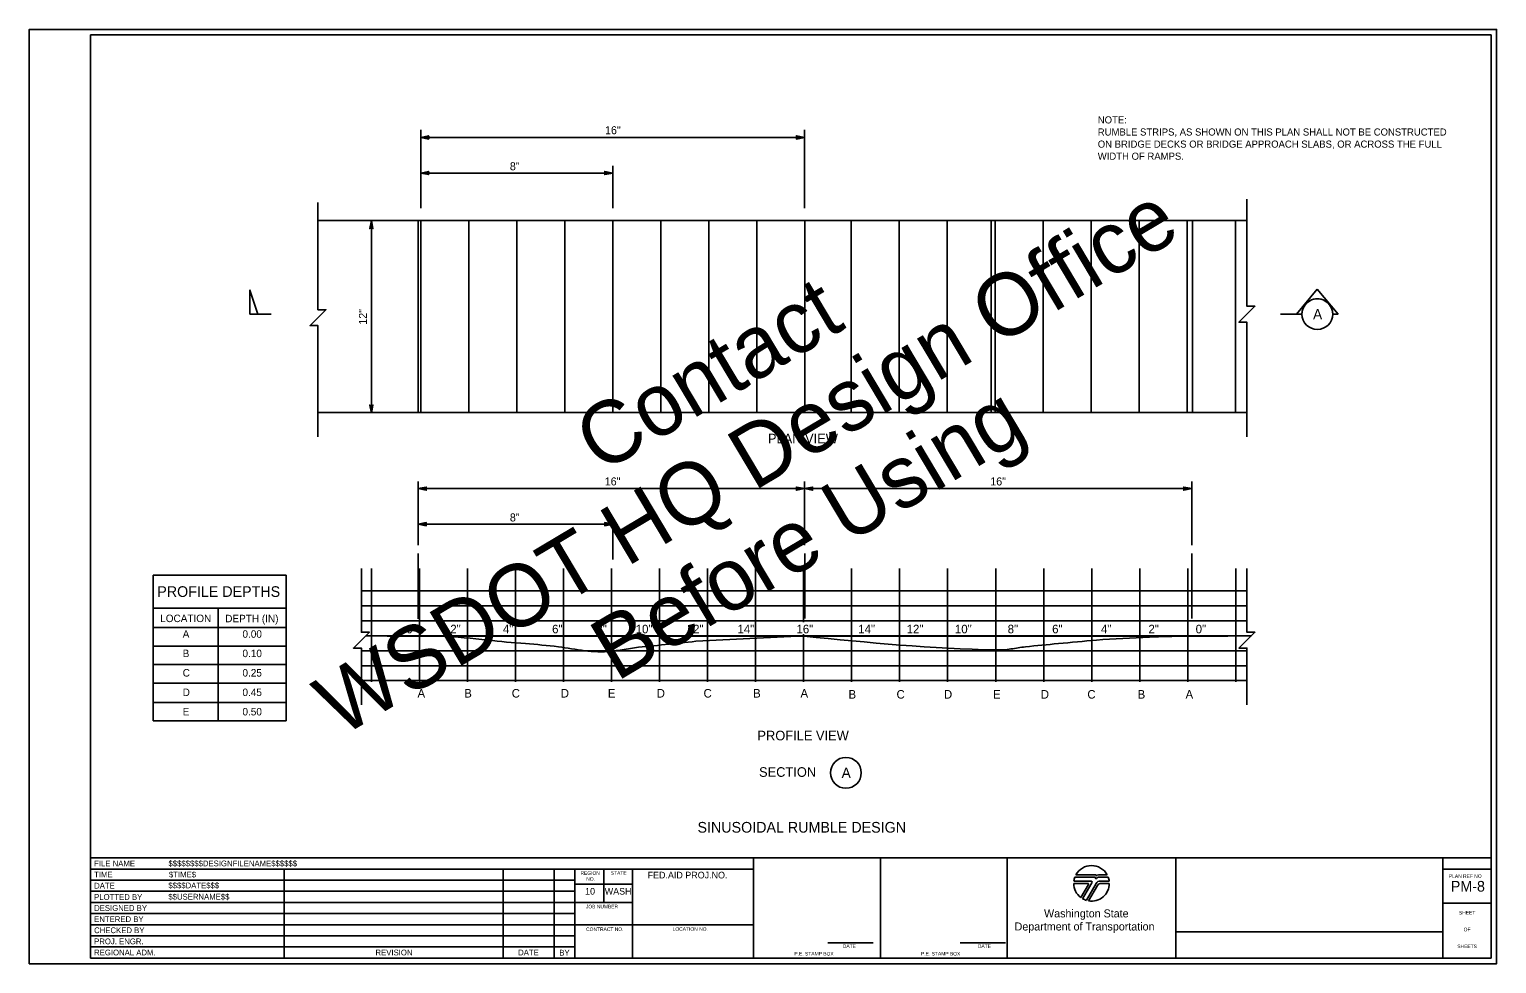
# Model space of a CAD drawing. Extents: x 100019.3 to 100035.8, y 99999.9 to 100024.4.
# Drawn here: x 100019.31 to 100035.81, y 99999.94 to 100010.44 of the extents above; entities that cross this region are included whole.
import ezdxf

# ---------------------------------------------------------------- set-up
doc = ezdxf.new("R2010")
doc.units = 0
for name, color, linetype in [('Level 10', 7, 'Continuous'), ('Level 15', 7, 'Continuous'), ('Level 16', 7, 'Continuous'), ('Level 20', 7, 'Continuous'), ('Level 22', 7, 'Continuous'), ('Level 25', 7, 'Continuous'), ('SH_GI_PlotLimits', 7, 'Continuous'), ('SH_GI_SheetBorder', 7, 'Continuous'), ('SH_GI_SheetTextInCells', 7, 'Continuous'), ('SH_GI_TitleBlockText', 7, 'Continuous'), ('SH_GI_WSDOTLogo', 7, 'Continuous')]:
    doc.layers.add(name, color=color, linetype=linetype)

msp = doc.modelspace()

# ---------------------------------------------------------------- linework, layer by layer
at = {"layer": 'Level 10'}
for p, q in [((100023.685, 100008.29), (100023.685, 100006.13)), ((100025.874, 100008.29), (100025.874, 100006.13)), ((100028.034, 100008.29), (100028.034, 100006.13)), ((100030.174, 100008.29), (100030.174, 100006.13)), ((100032.391, 100008.29), (100032.391, 100006.13)), ((100023.685, 100004.547), (100023.685, 100003.811)), ((100028.034, 100004.547), (100028.034, 100003.815)), ((100032.385, 100004.547), (100032.385, 100003.815))]:
    msp.add_line(p, q, dxfattribs=at)
at = {"layer": 'Level 15'}
for p, q in [((100023.713, 100008.427), (100023.713, 100009.308)), ((100028.029, 100008.427), (100028.029, 100009.308)), ((100028.029, 100009.223), (100023.713, 100009.223)), ((100025.874, 100008.823), (100023.713, 100008.823)), ((100025.874, 100008.427), (100025.874, 100008.903)), ((100023.159, 100008.29), (100023.159, 100006.124)), ((100025.874, 100008.29), (100025.874, 100006.13)), ((100023.685, 100004.641), (100023.685, 100005.355)), ((100028.029, 100004.641), (100028.029, 100005.355)), ((100032.385, 100005.355), (100032.385, 100004.64)), ((100028.029, 100005.276), (100023.685, 100005.276)), ((100032.385, 100005.276), (100028.029, 100005.276)), ((100025.874, 100004.876), (100023.685, 100004.876)), ((100025.874, 100004.48), (100025.874, 100004.956))]:
    msp.add_line(p, q, dxfattribs=at)
for points in [[(100023.713, 100009.223), (100023.803, 100009.205), (100023.799, 100009.223), (100023.803, 100009.241)], [(100028.029, 100009.223), (100027.938, 100009.241), (100027.943, 100009.223), (100027.938, 100009.205)], [(100023.713, 100008.823), (100023.803, 100008.805), (100023.799, 100008.823), (100023.803, 100008.841)], [(100025.874, 100008.823), (100025.783, 100008.841), (100025.787, 100008.823), (100025.783, 100008.805)], [(100023.159, 100008.29), (100023.176, 100008.199), (100023.159, 100008.203), (100023.141, 100008.199)], [(100023.159, 100006.124), (100023.176, 100006.215), (100023.159, 100006.21), (100023.141, 100006.215)], [(100023.685, 100005.276), (100023.776, 100005.258), (100023.771, 100005.276), (100023.776, 100005.294)], [(100028.029, 100005.276), (100027.938, 100005.294), (100027.943, 100005.276), (100027.938, 100005.258)], [(100028.029, 100005.276), (100028.12, 100005.258), (100028.115, 100005.276), (100028.12, 100005.294)], [(100032.385, 100005.276), (100032.294, 100005.294), (100032.299, 100005.276), (100032.294, 100005.258)], [(100023.685, 100004.876), (100023.776, 100004.858), (100023.771, 100004.876), (100023.776, 100004.894)], [(100025.874, 100004.876), (100025.783, 100004.894), (100025.787, 100004.876), (100025.783, 100004.858)]]:
    msp.add_lwpolyline(points, close=True, dxfattribs=at)
for points in [[(100022.558, 100008.491), (100022.558, 100007.286), (100022.647, 100007.286), (100022.469, 100007.108), (100022.558, 100007.108), (100022.558, 100005.857)], [(100033.004, 100008.529), (100033.004, 100007.325), (100033.094, 100007.325), (100032.915, 100007.146), (100033.004, 100007.146), (100033.004, 100005.857)], [(100023.047, 100004.378), (100023.047, 100003.662), (100023.136, 100003.662), (100022.957, 100003.483), (100023.047, 100003.483), (100023.047, 100002.847)], [(100033.004, 100004.378), (100033.004, 100003.662), (100033.094, 100003.662), (100032.915, 100003.483), (100033.004, 100003.483), (100033.004, 100002.847)]]:
    msp.add_lwpolyline(points, dxfattribs=at)
at = {"layer": 'Level 20'}
for p, q in [((100033.796, 100007.516), (100033.562, 100007.237)), ((100034.029, 100007.237), (100033.796, 100007.516)), ((100022.033, 100007.237), (100021.793, 100007.237)), ((100033.623, 100007.237), (100033.383, 100007.237)), ((100033.562, 100007.237), (100033.623, 100007.237)), ((100033.968, 100007.237), (100034.029, 100007.237)), ((100021.435, 100003.931), (100021.435, 100002.668))]:
    msp.add_line(p, q, dxfattribs=at)
msp.add_lwpolyline([(100021.883, 100007.237), (100021.793, 100007.507), (100021.793, 100007.237)], close=True, dxfattribs=at)
for centre in [(100033.796, 100007.237), (100028.495, 100002.082)]:
    msp.add_circle(centre, 0.173, dxfattribs=at)
msp.add_arc((100033.796, 100007.237), 0.173, 359.9978, 180.0022, dxfattribs=at)
at = {"layer": 'Level 22'}
for p, q in [((100023.401, 100003.618), (100028.019, 100003.618)), ((100032.128, 100003.618), (100027.217, 100003.618))]:
    msp.add_line(p, q, dxfattribs=at)
for points in [[(100023.096, 100003.622), (100023.735, 100003.618), (100023.938, 100003.618), (100024.466, 100003.573), (100024.892, 100003.534), (100025.262, 100003.498), (100025.852, 100003.447), (100025.931, 100003.458), (100026.119, 100003.487), (100026.464, 100003.523), (100026.809, 100003.56), (100027.416, 100003.59), (100028.027, 100003.618), (100028.041, 100003.618)], [(100032.791, 100003.618), (100032.312, 100003.618), (100031.908, 100003.607), (100031.311, 100003.573), (100030.884, 100003.534), (100030.514, 100003.498), (100030.432, 100003.487), (100030.35, 100003.474), (100030.268, 100003.464), (100030.186, 100003.463), (100028.027, 100003.618)]]:
    msp.add_spline(points, degree=3, dxfattribs=at)
at = {"layer": 'Level 25'}
for p, q in [((100022.558, 100008.29), (100033.004, 100008.29)), ((100023.713, 100008.29), (100023.713, 100006.13)), ((100024.253, 100008.29), (100024.253, 100006.13)), ((100024.794, 100008.29), (100024.794, 100006.13)), ((100025.334, 100008.29), (100025.334, 100006.13)), ((100026.414, 100008.29), (100026.414, 100006.13)), ((100026.954, 100008.29), (100026.954, 100006.13)), ((100027.494, 100008.29), (100027.494, 100006.13)), ((100028.554, 100008.29), (100028.554, 100006.13)), ((100029.094, 100008.29), (100029.094, 100006.13)), ((100029.634, 100008.29), (100029.634, 100006.13)), ((100030.13, 100008.29), (100030.13, 100006.13)), ((100030.714, 100008.29), (100030.714, 100006.13)), ((100031.254, 100008.29), (100031.254, 100006.13)), ((100031.794, 100008.29), (100031.794, 100006.13)), ((100032.334, 100008.29), (100032.334, 100006.13)), ((100032.874, 100008.29), (100032.874, 100006.13)), ((100022.558, 100006.13), (100033.004, 100006.13)), ((100023.159, 100003.106), (100023.159, 100004.378)), ((100023.699, 100003.106), (100023.699, 100004.378)), ((100024.239, 100003.106), (100024.239, 100004.378)), ((100024.779, 100003.106), (100024.779, 100004.378)), ((100025.319, 100003.106), (100025.319, 100004.378)), ((100025.859, 100003.106), (100025.859, 100004.378)), ((100026.399, 100003.106), (100026.399, 100004.378)), ((100026.939, 100003.106), (100026.939, 100004.378)), ((100027.479, 100003.106), (100027.479, 100004.378)), ((100028.019, 100003.774), (100028.019, 100004.378)), ((100028.559, 100003.106), (100028.559, 100004.378)), ((100029.099, 100003.106), (100029.099, 100004.378)), ((100029.639, 100003.106), (100029.639, 100004.378)), ((100030.179, 100003.106), (100030.179, 100004.378)), ((100030.719, 100003.106), (100030.719, 100004.378)), ((100031.259, 100003.106), (100031.259, 100004.378)), ((100031.799, 100003.106), (100031.799, 100004.378)), ((100032.339, 100003.106), (100032.339, 100004.378)), ((100032.879, 100003.106), (100032.879, 100004.378)), ((100023.047, 100004.126), (100029.099, 100004.126)), ((100029.099, 100004.126), (100033.004, 100004.126)), ((100020.706, 100003.931), (100022.199, 100003.931)), ((100023.047, 100003.958), (100029.099, 100003.958)), ((100029.099, 100003.958), (100033.004, 100003.958)), ((100020.706, 100003.715), (100022.199, 100003.715)), ((100023.047, 100003.79), (100029.099, 100003.79)), ((100029.099, 100003.79), (100033.004, 100003.79)), ((100023.096, 100003.622), (100029.099, 100003.622)), ((100028.019, 100003.106), (100028.019, 100003.639)), ((100029.099, 100003.622), (100033.054, 100003.622)), ((100020.706, 100003.507), (100022.199, 100003.507)), ((100023.047, 100003.454), (100029.099, 100003.454)), ((100029.099, 100003.454), (100033.004, 100003.454)), ((100020.706, 100003.299), (100022.199, 100003.299)), ((100023.047, 100003.286), (100029.099, 100003.286)), ((100029.099, 100003.286), (100033.004, 100003.286)), ((100020.706, 100003.09), (100022.199, 100003.09)), ((100023.047, 100003.118), (100029.099, 100003.118)), ((100029.099, 100003.118), (100033.004, 100003.118)), ((100020.706, 100002.874), (100022.199, 100002.874))]:
    msp.add_line(p, q, dxfattribs=at)
msp.add_lwpolyline([(100020.706, 100004.303), (100022.199, 100004.303), (100022.199, 100002.668), (100020.706, 100002.668)], close=True, dxfattribs=at)
at = {"layer": 'SH_GI_PlotLimits'}
msp.add_lwpolyline([(100019.312, 99999.937), (100035.812, 99999.937), (100035.812, 100010.437), (100019.312, 100010.437)], close=True, dxfattribs=at)
at = {"layer": 'SH_GI_SheetBorder'}
for p, q in [((100020, 100010.375), (100020, 100000)), ((100020, 100010.375), (100035.75, 100010.375)), ((100035.75, 100010.375), (100035.75, 100000)), ((100020, 100001.126), (100035.75, 100001.126)), ((100027.457, 100000), (100027.457, 100001.126)), ((100028.883, 100000), (100028.883, 100001.126)), ((100030.309, 100001.126), (100030.309, 100000)), ((100032.205, 100001.126), (100032.205, 100000)), ((100035.208, 100001.126), (100035.208, 100000)), ((100020, 100001.001), (100027.457, 100001.001)), ((100022.179, 100001.001), (100022.179, 100000)), ((100024.641, 100001.001), (100024.641, 100000)), ((100025.216, 100001.001), (100025.216, 100000)), ((100025.445, 100001.001), (100025.445, 100000)), ((100025.772, 100000.625), (100025.772, 100001.001)), ((100026.096, 100000), (100026.096, 100001.001)), ((100035.208, 100001.001), (100035.75, 100001.001)), ((100020, 100000.876), (100022.182, 100000.876)), ((100020, 100000.751), (100022.182, 100000.751)), ((100022.182, 100000.876), (100025.447, 100000.876)), ((100022.182, 100000.751), (100025.447, 100000.751)), ((100026.096, 100000.831), (100025.447, 100000.831)), ((100020, 100000.625), (100025.447, 100000.625)), ((100026.096, 100000.625), (100025.447, 100000.625)), ((100035.208, 100000.618), (100035.75, 100000.618)), ((100020, 100000.5), (100025.447, 100000.5)), ((100020, 100000.375), (100025.447, 100000.375)), ((100020, 100000.25), (100025.447, 100000.25)), ((100027.457, 100000.375), (100025.447, 100000.375)), ((100032.205, 100000.295), (100035.208, 100000.295)), ((100020, 100000.125), (100025.447, 100000.125)), ((100028.29, 100000.173), (100028.802, 100000.173)), ((100029.78, 100000.173), (100030.291, 100000.173)), ((100020, 100000), (100035.75, 100000))]:
    msp.add_line(p, q, dxfattribs=at)
at = {"layer": 'SH_GI_WSDOTLogo'}
for p, q in [((100031.289, 100000.909), (100031.07, 100000.909)), ((100031.303, 100000.935), (100031.081, 100000.935)), ((100031.433, 100000.935), (100031.335, 100000.935)), ((100031.445, 100000.909), (100031.343, 100000.909)), ((100031.343, 100000.909), (100031.343, 100000.909)), ((100031.057, 100000.84), (100031.215, 100000.84)), ((100031.059, 100000.866), (100031.25, 100000.866)), ((100031.222, 100000.828), (100031.136, 100000.681)), ((100031.261, 100000.846), (100031.157, 100000.667)), ((100031.199, 100000.649), (100031.309, 100000.839)), ((100031.224, 100000.643), (100031.324, 100000.816)), ((100031.356, 100000.866), (100031.456, 100000.866)), ((100031.365, 100000.839), (100031.457, 100000.839))]:
    msp.add_line(p, q, dxfattribs=at)
for centre, radius, start, end in [((100031.257, 100000.84), 0.2, 159.696, 172.5057), ((100031.257, 100000.84), 0.2, 28.4787, 151.532), ((100031.289, 100000.895), 0.0148, 327.8418, 89.9985), ((100031.343, 100000.861), 0.0484, 89.9953, 147.8238), ((100031.303, 100000.926), 0.00903, 329.8742, 90.0033), ((100031.335, 100000.907), 0.0287, 90.0072, 148.1676), ((100031.257, 100000.84), 0.2, 7.4943, 20.2941), ((100031.257, 100000.84), 0.2, 179.9986, 232.8433), ((100031.215, 100000.832), 0.0082, 329.7436, 90), ((100031.257, 100000.84), 0.2, 260.5455, 359.8086), ((100031.25, 100000.853), 0.0131, 329.7683, 90), ((100031.356, 100000.812), 0.0542, 90, 149.9974), ((100031.365, 100000.792), 0.0476, 90, 150.0543), ((100031.257, 100000.84), 0.2, 239.7929, 253.0448)]:
    msp.add_arc(centre, radius, start, end, dxfattribs=at)

# ---------------------------------------------------------------- texts
at = {"layer": 'Level 15'}
msp.add_text('SECTION ', height=0.108, dxfattribs=at).set_placement((100027.518, 100002.037))
at = {"layer": 'Level 16'}
for s, p in [('WSDOT HQ Design Office', (100022.812, 100002.475)), ('Contact ', (100025.736, 100005.438)), (' Before Using', (100025.692, 100002.968))]:
    msp.add_text(s, height=0.7, rotation=30.7778, dxfattribs=at).set_placement(p)
at = {"layer": 'Level 20'}
for s, height, p in [('16"', 0.09, (100025.786, 100009.259)), ('NOTE:', 0.08, (100031.327, 100009.38)), ('RUMBLE STRIPS, AS SHOWN ON THIS PLAN SHALL NOT BE CONSTRUCTED', 0.08, (100031.327, 100009.244)), ('ON BRIDGE DECKS OR BRIDGE APPROACH SLABS, OR ACROSS THE FULL', 0.08, (100031.327, 100009.108)), ('WIDTH OF RAMPS.', 0.08, (100031.327, 100008.972)), ('8"', 0.09, (100024.716, 100008.854)), ('A', 0.115, (100033.748, 100007.179)), ('PLAN VIEW', 0.108, (100027.618, 100005.785)), ('16"', 0.09, (100025.783, 100005.312)), ('16"', 0.09, (100030.118, 100005.312)), ('8"', 0.09, (100024.716, 100004.907)), ('PROFILE DEPTHS', 0.12, (100020.751, 100004.059)), ('LOCATION', 0.084, (100020.784, 100003.776)), ('DEPTH (IN)', 0.084, (100021.515, 100003.774)), ('0"', 0.096, (100023.552, 100003.65)), ('2"', 0.096, (100024.046, 100003.65)), ('4"', 0.096, (100024.638, 100003.65)), ('6"', 0.096, (100025.191, 100003.65)), ('8"', 0.096, (100025.689, 100003.65)), ('10"', 0.096, (100026.131, 100003.65)), ('12"', 0.096, (100026.706, 100003.65)), ('14"', 0.096, (100027.276, 100003.65)), ('14"', 0.096, (100028.634, 100003.65)), ('12"', 0.096, (100029.178, 100003.65)), ('10"', 0.096, (100029.721, 100003.65)), ('8"', 0.096, (100030.314, 100003.65)), ('6"', 0.096, (100030.814, 100003.65)), ('4"', 0.096, (100031.363, 100003.65)), ('2"', 0.096, (100031.897, 100003.65)), ('0"', 0.096, (100032.428, 100003.65)), ('A', 0.084, (100021.037, 100003.6)), ('0.00', 0.084, (100021.709, 100003.6)), ('B', 0.084, (100021.037, 100003.382)), ('0.10', 0.084, (100021.709, 100003.382)), ('C', 0.084, (100021.037, 100003.164)), ('0.25', 0.084, (100021.709, 100003.164)), ('D', 0.084, (100021.037, 100002.945)), ('0.45', 0.084, (100021.709, 100002.945)), ('A', 0.096, (100023.677, 100002.928)), ('B', 0.096, (100024.203, 100002.928)), ('C', 0.096, (100024.737, 100002.928)), ('D', 0.096, (100025.288, 100002.928)), ('E', 0.096, (100025.818, 100002.928)), ('D', 0.096, (100026.367, 100002.928)), ('C', 0.096, (100026.894, 100002.928)), ('B', 0.096, (100027.451, 100002.928)), ('A', 0.096, (100027.984, 100002.928)), ('B', 0.096, (100028.524, 100002.916)), ('C', 0.096, (100029.064, 100002.916)), ('D', 0.096, (100029.597, 100002.916)), ('E', 0.096, (100030.149, 100002.916)), ('D', 0.096, (100030.686, 100002.916)), ('C', 0.096, (100031.21, 100002.916)), ('B', 0.096, (100031.775, 100002.916)), ('A', 0.096, (100032.314, 100002.916)), ('E', 0.084, (100021.037, 100002.727)), ('0.50', 0.084, (100021.709, 100002.727)), ('PROFILE VIEW', 0.108, (100027.5, 100002.447)), ('A', 0.115, (100028.447, 100002.025)), ('SINUSOIDAL RUMBLE DESIGN', 0.12, (100026.826, 100001.41)), ('PM-8', 0.12, (100035.297, 100000.747))]:
    msp.add_text(s, height=height, dxfattribs=at).set_placement(p)
msp.add_text('12"', height=0.09, rotation=90, dxfattribs=at).set_placement((100023.109, 100007.118))
at = {"layer": 'Level 25'}
msp.add_text('16"', height=0.096, dxfattribs=at).set_placement((100027.939, 100003.65))
at = {"layer": 'SH_GI_SheetBorder'}
msp.add_text('PLAN REF NO', height=0.04003, dxfattribs=at).set_placement((100035.275, 100000.901))
at = {"layer": 'SH_GI_SheetTextInCells'}
for s, height, p in [('FILE NAME', 0.0651, (100020.041, 100001.031)), ('TIME', 0.0651, (100020.041, 100000.906)), ('REGION', 0.04, (100025.51, 100000.935)), ('NO.', 0.04, (100025.575, 100000.869)), ('STATE', 0.04, (100025.851, 100000.936)), ('FED.AID PROJ.NO.', 0.07506, (100026.265, 100000.895)), ('DATE', 0.0651, (100020.041, 100000.781)), ('10', 0.0751, (100025.562, 100000.713)), ('WASH', 0.0751, (100025.783, 100000.713)), ('PLOTTED BY', 0.0651, (100020.041, 100000.654)), ('DESIGNED BY', 0.06505, (100020.041, 100000.53)), ('JOB NUMBER', 0.04, (100025.571, 100000.559)), ('ENTERED BY', 0.0651, (100020.041, 100000.405)), ('Department of Transportation', 0.09007, (100030.392, 100000.31)), ('Washington State', 0.09007, (100030.723, 100000.457)), ('SHEET', 0.04, (100035.388, 100000.49)), ('CHECKED BY', 0.0651, (100020.041, 100000.28)), ('CONTRACT NO.', 0.04003, (100025.573, 100000.304)), ('LOCATION NO.', 0.04003, (100026.546, 100000.307)), ('OF', 0.04, (100035.441, 100000.301)), ('PROJ. ENGR.', 0.06505, (100020.041, 100000.155)), ('REGIONAL ADM.', 0.06505, (100020.041, 100000.03)), ('REVISION', 0.0651, (100023.205, 100000.03)), ('DATE', 0.0651, (100024.809, 100000.03)), ('BY', 0.0651, (100025.272, 100000.028)), ('P.E. STAMP BOX', 0.04003, (100027.915, 100000.029)), ('DATE', 0.04, (100028.46, 100000.114)), ('P.E. STAMP BOX', 0.04003, (100029.339, 100000.029)), ('DATE', 0.04, (100029.979, 100000.114)), ('SHEETS', 0.04, (100035.37, 100000.112))]:
    msp.add_text(s, height=height, dxfattribs=at).set_placement(p)
at = {"layer": 'SH_GI_TitleBlockText'}
for s, height, p in [('$$$$$$$$DESIGNFILENAME$$$$$$', 0.06505, (100020.877, 100001.031)), ('$TIME$', 0.0651, (100020.882, 100000.906)), ('$$$$DATE$$$', 0.06505, (100020.876, 100000.784)), ('$$USERNAME$$', 0.06505, (100020.876, 100000.657))]:
    msp.add_text(s, height=height, dxfattribs=at).set_placement(p)

doc.saveas('drawing.dxf')
